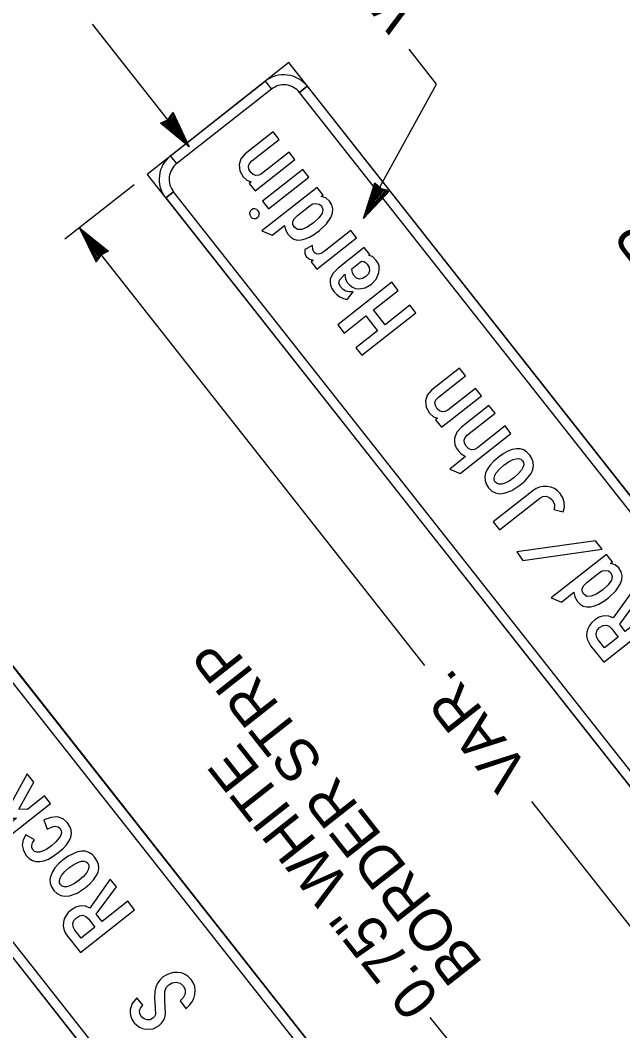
# Model space of a CAD drawing. Extents: x 671946 to 673995, y 1673066 to 1674936.
# Drawn here: x 672488.3 to 672548.4, y 1673831.7 to 1673932.5 of the extents above; entities that cross this region are included whole.
import ezdxf

# ---------------------------------------------------------------- set-up
doc = ezdxf.new("R2010")
doc.units = 0
doc.layers.add('C-ANNO-SYMB', color=7, linetype='Continuous')
doc.layers.add('Level 1', color=7, linetype='Continuous')

msp = doc.modelspace()

# ---------------------------------------------------------------- linework, layer by layer
at = {"layer": 'C-ANNO-SYMB'}
for p, q in [((672515.08, 1673928.32), (672500.95, 1673917.17)), ((672593.09, 1673829.37), (672515.08, 1673928.32)), ((672503.3, 1673919.03), (672512.73, 1673926.46)), ((672512.73, 1673926.46), (672513.35, 1673925.68)), ((672512.73, 1673926.46), (672513.35, 1673925.68)), ((672513.35, 1673925.68), (672503.92, 1673918.25)), ((672513.35, 1673925.68), (672513.35, 1673925.68)), ((672513.35, 1673925.68), (672513.35, 1673925.68)), ((672516.16, 1673925.34), (672516.94, 1673925.96)), ((672516.94, 1673925.96), (672516.16, 1673925.34)), ((672516.94, 1673925.96), (672591.23, 1673831.72)), ((672590.45, 1673831.11), (672516.16, 1673925.34)), ((672503.92, 1673918.25), (672503.3, 1673919.03)), ((672503.92, 1673918.25), (672503.3, 1673919.03)), ((672503.92, 1673918.25), (672503.3, 1673919.03)), ((672500.95, 1673917.17), (672578.96, 1673818.23)), ((672502.81, 1673914.82), (672503.59, 1673915.44)), ((672503.59, 1673915.44), (672502.81, 1673914.82)), ((672503.59, 1673915.44), (672503.59, 1673915.44)), ((672503.59, 1673915.44), (672503.59, 1673915.44)), ((672577.88, 1673821.2), (672503.59, 1673915.44)), ((672502.81, 1673914.82), (672577.1, 1673820.58)), ((672546.83, 1673792.9), (672468.82, 1673891.85)), ((672470.68, 1673889.49), (672544.97, 1673795.25)), ((672544.19, 1673794.63), (672469.89, 1673888.87)), ((672454.69, 1673880.7), (672532.69, 1673781.75)), ((672456.54, 1673878.35), (672530.83, 1673784.11)), ((672531.62, 1673784.73), (672457.33, 1673878.97))]:
    msp.add_line(p, q, dxfattribs=at)
for points in [[(672515.71, 1673918.65), (672515.13, 1673919.39), (672512.38, 1673917.23), (672512.11, 1673917.08), (672511.82, 1673917.05), (672511.54, 1673917.15), (672511.3, 1673917.36), (672511.12, 1673917.68), (672511.07, 1673917.98), (672511.18, 1673918.26), (672511.42, 1673918.52), (672514.13, 1673920.66), (672513.52, 1673921.42), (672510.73, 1673919.22), (672510.31, 1673918.73), (672510.14, 1673918.14), (672510.22, 1673917.52), (672510.55, 1673916.93), (672510.92, 1673916.58), (672511.33, 1673916.41), (672511.15, 1673916.27), (672511.74, 1673915.52)], [(672517.1, 1673916.89), (672516.5, 1673917.65), (672512.48, 1673914.49), (672513.08, 1673913.72)], [(672511.98, 1673912.86), (672512.1, 1673912.99), (672512.15, 1673913.17), (672512.13, 1673913.36), (672512.04, 1673913.53), (672511.89, 1673913.66), (672511.71, 1673913.73), (672511.53, 1673913.72), (672511.37, 1673913.63), (672511.24, 1673913.49), (672511.18, 1673913.31), (672511.2, 1673913.12), (672511.3, 1673912.94), (672511.44, 1673912.81), (672511.63, 1673912.76), (672511.81, 1673912.77)], [(672521.86, 1673910.84), (672521.28, 1673911.58), (672518.63, 1673909.48), (672518.32, 1673909.28), (672518.05, 1673909.2), (672517.82, 1673909.24), (672517.62, 1673909.39), (672517.49, 1673909.69), (672517.46, 1673910.08), (672516.69, 1673909.67), (672516.7, 1673909.26), (672516.84, 1673908.96), (672517.15, 1673908.7), (672517.51, 1673908.61), (672517.31, 1673908.45), (672517.9, 1673907.71)], [(672527.76, 1673903.37), (672527.18, 1673904.11), (672524.7, 1673902.16), (672523.53, 1673903.64), (672526.01, 1673905.59), (672525.36, 1673906.41), (672519.97, 1673902.16), (672520.62, 1673901.34), (672522.78, 1673903.04), (672523.95, 1673901.56), (672521.78, 1673899.86), (672522.37, 1673899.12)], [(672534.3, 1673895.07), (672533.72, 1673895.81), (672530.97, 1673893.64), (672530.7, 1673893.5), (672530.41, 1673893.47), (672530.13, 1673893.57), (672529.9, 1673893.78), (672529.71, 1673894.1), (672529.67, 1673894.4), (672529.77, 1673894.68), (672530.01, 1673894.94), (672532.72, 1673897.08), (672532.12, 1673897.84), (672529.32, 1673895.64), (672528.9, 1673895.15), (672528.73, 1673894.56), (672528.81, 1673893.94), (672529.14, 1673893.35), (672529.51, 1673892.99), (672529.92, 1673892.83), (672529.74, 1673892.69), (672530.33, 1673891.94)], [(672532.32, 1673891.94), (672531.86, 1673891.44), (672531.63, 1673890.85), (672531.61, 1673890.52), (672531.66, 1673890.21), (672531.78, 1673889.9), (672531.97, 1673889.61), (672532.29, 1673889.3), (672532.72, 1673889.01), (672531.14, 1673887.77), (672532.17, 1673887.32), (672537.25, 1673891.33), (672536.67, 1673892.07), (672533.92, 1673889.9), (672533.62, 1673889.73), (672533.33, 1673889.69), (672533.06, 1673889.79), (672532.8, 1673890.04), (672532.62, 1673890.35), (672532.58, 1673890.64), (672532.68, 1673890.92), (672532.92, 1673891.17), (672535.67, 1673893.34), (672535.06, 1673894.1)], [(672542.45, 1673883.49), (672542.58, 1673883.95), (672542.55, 1673884.45), (672542.41, 1673884.91), (672542.15, 1673885.33), (672541.88, 1673885.61), (672541.58, 1673885.83), (672541.24, 1673885.97), (672540.86, 1673886.04), (672540.47, 1673886.04), (672540.11, 1673885.96), (672539.76, 1673885.82), (672539.43, 1673885.6), (672535.48, 1673882.49), (672536.1, 1673881.7), (672540.12, 1673884.88), (672540.43, 1673885.04), (672540.78, 1673885.05), (672541.11, 1673884.94), (672541.37, 1673884.71), (672541.51, 1673884.48), (672541.58, 1673884.24), (672541.59, 1673883.98), (672541.52, 1673883.72)], [(672546.35, 1673879.79), (672545.69, 1673880.62), (672537.83, 1673879.5), (672538.45, 1673878.63)], [(672491.33, 1673854.41), (672490.74, 1673855.15), (672489.03, 1673853.8), (672488.17, 1673853.83), (672489.66, 1673856.53), (672489.01, 1673857.35), (672487.06, 1673853.82), (672485.28, 1673853.82), (672486.04, 1673852.95), (672487.92, 1673852.93), (672485.25, 1673850.82), (672486.25, 1673850.41)], [(672490.99, 1673851.84), (672491.42, 1673852.05), (672491.78, 1673852.13), (672492.08, 1673852.07), (672492.3, 1673851.89), (672492.4, 1673851.7), (672492.42, 1673851.48), (672492.35, 1673851.23), (672492.18, 1673850.96), (672491.87, 1673850.57), (672491.43, 1673850.19), (672490.96, 1673849.86), (672490.51, 1673849.64), (672490.21, 1673849.55), (672489.95, 1673849.54), (672489.74, 1673849.6), (672489.58, 1673849.74), (672489.46, 1673849.97), (672489.45, 1673850.21), (672489.54, 1673850.48), (672489.74, 1673850.76), (672488.86, 1673851.26), (672488.59, 1673850.77), (672488.51, 1673850.25), (672488.62, 1673849.72), (672488.91, 1673849.22), (672489.2, 1673848.92), (672489.52, 1673848.72), (672489.87, 1673848.61), (672490.25, 1673848.6), (672490.67, 1673848.68), (672491.11, 1673848.86), (672491.59, 1673849.13), (672492.1, 1673849.5), (672492.56, 1673849.89), (672492.92, 1673850.28), (672493.18, 1673850.66), (672493.34, 1673851.04), (672493.41, 1673851.4), (672493.38, 1673851.77), (672493.26, 1673852.12), (672493.03, 1673852.47), (672492.57, 1673852.88), (672492.02, 1673853.07), (672491.38, 1673853.02), (672490.65, 1673852.76)], [(672504.83, 1673833.95), (672504.88, 1673833.99), (672505.19, 1673834.27), (672505.43, 1673834.59), (672505.61, 1673834.94), (672505.72, 1673835.33), (672505.76, 1673835.74), (672505.71, 1673836.13), (672505.58, 1673836.49), (672505.35, 1673836.84), (672505.07, 1673837.14), (672504.75, 1673837.35), (672504.39, 1673837.49), (672503.99, 1673837.55), (672503.6, 1673837.54), (672503.22, 1673837.45), (672502.86, 1673837.29), (672502.51, 1673837.06), (672502.22, 1673836.78), (672502, 1673836.46), (672501.84, 1673836.08), (672501.74, 1673835.66), (672501.71, 1673834.98), (672501.77, 1673834.01), (672501.79, 1673833.36), (672501.7, 1673833.14), (672501.54, 1673832.97), (672501.27, 1673832.83), (672500.95, 1673832.81), (672500.65, 1673832.92), (672500.4, 1673833.13), (672500.24, 1673833.43), (672500.21, 1673833.73), (672500.31, 1673833.98), (672500.52, 1673834.27), (672499.93, 1673835.02), (672499.47, 1673834.46), (672499.27, 1673833.84), (672499.26, 1673833.49), (672499.33, 1673833.16), (672499.47, 1673832.83), (672499.67, 1673832.52), (672499.92, 1673832.27), (672500.19, 1673832.08), (672500.51, 1673831.94), (672500.86, 1673831.88), (672501.55, 1673831.92), (672502.16, 1673832.24), (672502.41, 1673832.48), (672502.6, 1673832.75), (672502.72, 1673833.06), (672502.79, 1673833.4), (672502.72, 1673834.77), (672502.71, 1673835.29), (672502.74, 1673835.64), (672502.87, 1673836.03), (672503.11, 1673836.32), (672503.47, 1673836.52), (672503.86, 1673836.58), (672504.26, 1673836.48), (672504.57, 1673836.22), (672504.76, 1673835.83), (672504.74, 1673835.4), (672504.56, 1673835.02), (672504.24, 1673834.7)]]:
    msp.add_lwpolyline(points, close=True, dxfattribs=at)
for points in [[(672518.51, 1673915.11), (672517.91, 1673915.87), (672512.4, 1673911.54), (672513.43, 1673911.1), (672514.67, 1673912.08), (672514.76, 1673911.63), (672515.04, 1673911.16), (672515.31, 1673910.89), (672515.61, 1673910.71), (672515.94, 1673910.62), (672516.31, 1673910.63), (672516.72, 1673910.73), (672517.16, 1673910.92), (672517.64, 1673911.2), (672518.14, 1673911.57), (672518.85, 1673912.22), (672519.3, 1673912.88), (672519.45, 1673913.31), (672519.48, 1673913.73), (672519.38, 1673914.13), (672519.15, 1673914.51), (672518.78, 1673914.82), (672518.32, 1673914.96), (672518.51, 1673915.11)], [(672517.21, 1673914.06), (672517.49, 1673914.22), (672517.8, 1673914.27), (672518.12, 1673914.21), (672518.36, 1673914.02), (672518.5, 1673913.67), (672518.41, 1673913.28), (672518.09, 1673912.83), (672517.55, 1673912.34), (672516.91, 1673911.9), (672516.38, 1673911.68), (672515.97, 1673911.67), (672515.66, 1673911.89), (672515.51, 1673912.18), (672515.51, 1673912.47), (672515.66, 1673912.77), (672515.96, 1673913.07), (672517.21, 1673914.06)], [(672523.18, 1673909.17), (672522.62, 1673909.88), (672520, 1673907.81), (672519.49, 1673907.29), (672519.23, 1673906.73), (672519.21, 1673906.41), (672519.25, 1673906.1), (672519.38, 1673905.78), (672519.59, 1673905.47), (672519.87, 1673905.17), (672520.19, 1673904.94), (672520.54, 1673904.78), (672520.93, 1673904.68), (672521.5, 1673905.45), (672521.12, 1673905.45), (672520.79, 1673905.53), (672520.51, 1673905.68), (672520.27, 1673905.91), (672520.08, 1673906.29), (672520.14, 1673906.63), (672520.68, 1673907.2), (672520.76, 1673906.72), (672520.95, 1673906.36), (672521.19, 1673906.1), (672521.46, 1673905.91), (672521.76, 1673905.79), (672522.08, 1673905.75), (672522.72, 1673905.85), (672523.34, 1673906.21), (672523.81, 1673906.72), (672524.08, 1673907.34), (672524.12, 1673907.68), (672524.1, 1673908), (672523.99, 1673908.31), (672523.81, 1673908.59), (672523.44, 1673908.96), (672523.07, 1673909.09), (672523.18, 1673909.17)], [(672521.38, 1673907.76), (672522.21, 1673908.41), (672522.38, 1673908.5), (672522.56, 1673908.49), (672522.74, 1673908.39), (672522.92, 1673908.2), (672523.1, 1673907.88), (672523.14, 1673907.55), (672523.03, 1673907.24), (672522.78, 1673906.97), (672522.45, 1673906.77), (672522.14, 1673906.72), (672521.86, 1673906.81), (672521.61, 1673907.04), (672521.44, 1673907.36), (672521.38, 1673907.76)], [(672535.96, 1673888.93), (672535.5, 1673888.53), (672535.13, 1673888.13), (672534.87, 1673887.74), (672534.7, 1673887.36), (672534.64, 1673886.98), (672534.67, 1673886.61), (672534.8, 1673886.24), (672535.02, 1673885.89), (672535.35, 1673885.57), (672535.71, 1673885.38), (672536.13, 1673885.3), (672536.59, 1673885.35), (672537.34, 1673885.63), (672538.15, 1673886.15), (672538.62, 1673886.56), (672538.98, 1673886.95), (672539.26, 1673887.34), (672539.43, 1673887.72), (672539.5, 1673888.1), (672539.47, 1673888.46), (672539.35, 1673888.82), (672539.12, 1673889.17), (672538.84, 1673889.47), (672538.52, 1673889.67), (672538.17, 1673889.79), (672537.79, 1673889.8), (672537.38, 1673889.73), (672536.94, 1673889.55), (672536.46, 1673889.29), (672535.96, 1673888.93)], [(672536.53, 1673888.15), (672537.01, 1673888.48), (672537.46, 1673888.71), (672537.77, 1673888.8), (672538.02, 1673888.81), (672538.24, 1673888.75), (672538.4, 1673888.6), (672538.51, 1673888.41), (672538.52, 1673888.19), (672538.45, 1673887.94), (672538.3, 1673887.66), (672537.98, 1673887.28), (672537.54, 1673886.89), (672537.07, 1673886.57), (672536.63, 1673886.35), (672536.33, 1673886.26), (672536.07, 1673886.25), (672535.86, 1673886.32), (672535.69, 1673886.46), (672535.59, 1673886.66), (672535.58, 1673886.87), (672535.64, 1673887.12), (672535.79, 1673887.39), (672536.11, 1673887.77), (672536.53, 1673888.15)], [(672547.37, 1673878.5), (672546.77, 1673879.26), (672541.27, 1673874.93), (672542.29, 1673874.49), (672543.54, 1673875.47), (672543.62, 1673875.02), (672543.9, 1673874.55), (672544.17, 1673874.28), (672544.47, 1673874.1), (672544.81, 1673874.01), (672545.18, 1673874.02), (672545.58, 1673874.12), (672546.02, 1673874.3), (672546.5, 1673874.58), (672547.01, 1673874.95), (672547.71, 1673875.61), (672548.16, 1673876.27), (672548.31, 1673876.7), (672548.34, 1673877.12), (672548.24, 1673877.52), (672548.01, 1673877.9), (672547.64, 1673878.2), (672547.18, 1673878.35), (672547.37, 1673878.5)], [(672546.07, 1673877.44), (672546.35, 1673877.6), (672546.66, 1673877.66), (672546.98, 1673877.6), (672547.22, 1673877.41), (672547.36, 1673877.06), (672547.27, 1673876.67), (672546.96, 1673876.22), (672546.41, 1673875.73), (672545.77, 1673875.29), (672545.25, 1673875.07), (672544.83, 1673875.06), (672544.52, 1673875.28), (672544.37, 1673875.57), (672544.37, 1673875.86), (672544.52, 1673876.16), (672544.82, 1673876.46), (672546.07, 1673877.44)], [(672551.9, 1673872.75), (672551.23, 1673873.59), (672548.66, 1673871.57), (672548.1, 1673872.29), (672550.11, 1673875.02), (672549.5, 1673875.79), (672547.46, 1673872.91), (672547.01, 1673873.1), (672546.51, 1673873.12), (672546.05, 1673872.99), (672545.62, 1673872.73), (672545.31, 1673872.45), (672545.07, 1673872.16), (672544.91, 1673871.84), (672544.82, 1673871.51), (672544.8, 1673871.16), (672544.86, 1673870.8), (672545.01, 1673870.45), (672545.23, 1673870.11), (672546.51, 1673868.5), (672551.9, 1673872.75)], [(672547.95, 1673871.01), (672546.58, 1673869.93), (672545.96, 1673870.72), (672545.78, 1673871.03), (672545.75, 1673871.36), (672545.86, 1673871.68), (672546.1, 1673871.95), (672546.44, 1673872.15), (672546.75, 1673872.19), (672547.04, 1673872.08), (672547.31, 1673871.83), (672547.95, 1673871.01)], [(672492.6, 1673848.77), (672492.13, 1673848.37), (672491.77, 1673847.97), (672491.51, 1673847.58), (672491.34, 1673847.2), (672491.27, 1673846.82), (672491.3, 1673846.45), (672491.43, 1673846.09), (672491.66, 1673845.73), (672491.98, 1673845.41), (672492.35, 1673845.22), (672492.76, 1673845.14), (672493.22, 1673845.19), (672493.98, 1673845.47), (672494.78, 1673845.99), (672495.25, 1673846.4), (672495.62, 1673846.79), (672495.89, 1673847.18), (672496.06, 1673847.56), (672496.14, 1673847.94), (672496.11, 1673848.3), (672495.98, 1673848.66), (672495.76, 1673849.01), (672495.47, 1673849.31), (672495.15, 1673849.52), (672494.8, 1673849.63), (672494.42, 1673849.64), (672494.01, 1673849.57), (672493.57, 1673849.39), (672493.1, 1673849.13), (672492.6, 1673848.77)], [(672493.16, 1673847.99), (672493.64, 1673848.33), (672494.1, 1673848.56), (672494.4, 1673848.64), (672494.66, 1673848.65), (672494.87, 1673848.59), (672495.04, 1673848.44), (672495.14, 1673848.25), (672495.15, 1673848.03), (672495.09, 1673847.78), (672494.93, 1673847.51), (672494.62, 1673847.12), (672494.18, 1673846.74), (672493.71, 1673846.41), (672493.26, 1673846.19), (672492.96, 1673846.1), (672492.7, 1673846.09), (672492.49, 1673846.16), (672492.33, 1673846.31), (672492.23, 1673846.5), (672492.21, 1673846.72), (672492.28, 1673846.96), (672492.42, 1673847.23), (672492.74, 1673847.61), (672493.16, 1673847.99)], [(672499.69, 1673843.8), (672499.02, 1673844.65), (672496.46, 1673842.63), (672495.89, 1673843.35), (672497.9, 1673846.07), (672497.29, 1673846.85), (672495.25, 1673843.97), (672494.8, 1673844.16), (672494.3, 1673844.18), (672493.84, 1673844.05), (672493.41, 1673843.79), (672493.1, 1673843.51), (672492.87, 1673843.21), (672492.7, 1673842.9), (672492.61, 1673842.57), (672492.59, 1673842.21), (672492.66, 1673841.86), (672492.8, 1673841.51), (672493.03, 1673841.17), (672494.3, 1673839.55), (672499.69, 1673843.8)], [(672495.75, 1673842.07), (672494.37, 1673840.98), (672493.75, 1673841.77), (672493.58, 1673842.09), (672493.54, 1673842.42), (672493.65, 1673842.74), (672493.9, 1673843.01), (672494.23, 1673843.2), (672494.54, 1673843.25), (672494.83, 1673843.14), (672495.1, 1673842.88), (672495.75, 1673842.07)]]:
    msp.add_lwpolyline(points, dxfattribs=at)
for centre, radius, start, end in [((672514.59, 1673924.1), 3, 38.2506, 128.2508), ((672514.59, 1673924.1), 2, 38.2506, 128.2508), ((672505.16, 1673916.68), 3, 128.2505, 218.2508), ((672505.16, 1673916.68), 2, 128.2505, 218.2508)]:
    msp.add_arc(centre, radius, start, end, dxfattribs=at)
at = {"layer": 'Level 1'}
for p, q in [((672505.16, 1673919.91), (672495.5, 1673932.16)), ((672503.52, 1673923.4), (672505.16, 1673919.91)), ((672502.3, 1673922.29), (672503.06, 1673922.66)), ((672502.44, 1673922.27), (672503.02, 1673922.6)), ((672502.61, 1673922.26), (672502.87, 1673922.39)), ((672502.74, 1673922.26), (672503.46, 1673922.92)), ((672502.87, 1673922.39), (672503.46, 1673922.92)), ((672502.88, 1673922.3), (672503.39, 1673922.75)), ((672503.29, 1673922.67), (672503.01, 1673922.3)), ((672503.02, 1673922.6), (672503.5, 1673923.26)), ((672503.02, 1673922.24), (672503.35, 1673922.59)), ((672503.06, 1673922.66), (672503.38, 1673922.9)), ((672503.15, 1673922.2), (672503.3, 1673922.48)), ((672503.29, 1673922.31), (672503.29, 1673922.67)), ((672503.3, 1673922.48), (672503.56, 1673921.96)), ((672503.35, 1673922.59), (672503.85, 1673921.61)), ((672503.38, 1673922.9), (672503.57, 1673923.21)), ((672503.39, 1673922.75), (672504.11, 1673921.22)), ((672503.5, 1673923.26), (672503.43, 1673923.04)), ((672503.43, 1673923.04), (672503.53, 1673923.04)), ((672503.46, 1673922.92), (672504.44, 1673920.78)), ((672503.46, 1673922.92), (672504.56, 1673920.71)), ((672503.53, 1673923.04), (672504.89, 1673920.17)), ((672503.57, 1673923.21), (672504.8, 1673920.33)), ((672505.16, 1673919.91), (672502.3, 1673922.29)), ((672504.92, 1673920.13), (672502.44, 1673922.27)), ((672504.66, 1673920.49), (672502.61, 1673922.26)), ((672504.44, 1673920.78), (672502.74, 1673922.26)), ((672504.56, 1673920.71), (672502.88, 1673922.3)), ((672503.01, 1673922.3), (672503.76, 1673921.78)), ((672504.11, 1673921.22), (672503.02, 1673922.24)), ((672503.85, 1673921.61), (672503.15, 1673922.2)), ((672503.22, 1673922.23), (672503.29, 1673922.31)), ((672503.56, 1673921.96), (672503.22, 1673922.23)), ((672503.76, 1673921.78), (672503.85, 1673921.52)), ((672522.54, 1673912.78), (672523.66, 1673916.33)), ((672523.66, 1673916.33), (672524.3, 1673915.76)), ((672499.66, 1673916.14), (672492.76, 1673910.7)), ((672525.2, 1673915.58), (672522.54, 1673912.78)), ((672522.66, 1673913.08), (672523.7, 1673916.18)), ((672524.83, 1673915.47), (672522.69, 1673913.12)), ((672525, 1673915.5), (672522.81, 1673913.27)), ((672522.89, 1673913.46), (672523.75, 1673916.03)), ((672523.06, 1673913.63), (672523.89, 1673915.79)), ((672524.69, 1673915.5), (672523.06, 1673913.63)), ((672523.08, 1673913.78), (672523.8, 1673915.9)), ((672524.69, 1673915.5), (672523.08, 1673913.78)), ((672523.36, 1673914.25), (672523.89, 1673915.64)), ((672524.5, 1673915.49), (672523.36, 1673914.25)), ((672523.63, 1673914.64), (672523.9, 1673915.51)), ((672524.34, 1673915.47), (672523.63, 1673914.64)), ((672523.7, 1673916.18), (672524.22, 1673915.78)), ((672523.94, 1673915.67), (672523.74, 1673914.78)), ((672523.75, 1673916.03), (672523.98, 1673915.83)), ((672523.8, 1673915.9), (672524.69, 1673915.5)), ((672524.22, 1673915.47), (672523.83, 1673915.04)), ((672523.83, 1673915.04), (672523.96, 1673915.45)), ((672523.89, 1673915.79), (672524.5, 1673915.49)), ((672523.89, 1673915.64), (672524.34, 1673915.47)), ((672523.9, 1673915.51), (672524.22, 1673915.47)), ((672524.39, 1673915.56), (672523.94, 1673915.67)), ((672523.96, 1673915.45), (672524.06, 1673915.42)), ((672523.98, 1673915.83), (672524.69, 1673915.5)), ((672524.06, 1673915.42), (672524.39, 1673915.56)), ((672524.22, 1673915.78), (672525.01, 1673915.58)), ((672524.3, 1673915.76), (672524.64, 1673915.56)), ((672524.64, 1673915.56), (672525, 1673915.5)), ((672524.79, 1673915.56), (672524.83, 1673915.47)), ((672523.54, 1673914.6), (672523.33, 1673914.14)), ((672523.33, 1673914.14), (672523.66, 1673914.49)), ((672523.74, 1673914.78), (672523.54, 1673914.6)), ((672522.87, 1673913.23), (672523.46, 1673913.91)), ((672523.46, 1673913.91), (672522.89, 1673913.46)), ((672495.91, 1673908.37), (672494.2, 1673911.84)), ((672494.2, 1673911.84), (672497.11, 1673909.51)), ((672528.67, 1673868.18), (672494.24, 1673911.86)), ((672494.56, 1673911.41), (672494.44, 1673911.62)), ((672494.44, 1673911.62), (672496.96, 1673909.53)), ((672495.89, 1673908.73), (672494.47, 1673911.58)), ((672494.47, 1673911.58), (672494.5, 1673911.37)), ((672494.5, 1673911.37), (672494.92, 1673910.57)), ((672495.85, 1673908.57), (672494.56, 1673911.41)), ((672494.92, 1673910.57), (672494.71, 1673911.27)), ((672494.71, 1673911.27), (672496.79, 1673909.53)), ((672495.96, 1673908.85), (672494.81, 1673911.05)), ((672494.81, 1673911.05), (672496.53, 1673909.49)), ((672495.96, 1673908.85), (672494.94, 1673910.98)), ((672494.94, 1673910.98), (672496.66, 1673909.53)), ((672495.54, 1673910.25), (672495.19, 1673910.61)), ((672495.19, 1673910.61), (672495.4, 1673910.17)), ((672496.02, 1673909.03), (672495.28, 1673910.54)), ((672495.28, 1673910.54), (672496.38, 1673909.55)), ((672495.64, 1673909.99), (672495.54, 1673910.25)), ((672496.06, 1673909.19), (672495.55, 1673910.15)), ((672495.55, 1673910.15), (672496.26, 1673909.58)), ((672496.4, 1673909.49), (672495.64, 1673909.99)), ((672496.11, 1673909.3), (672495.84, 1673909.82)), ((672495.84, 1673909.82), (672496.18, 1673909.55)), ((672496.66, 1673909.53), (672495.96, 1673908.85)), ((672496.53, 1673909.4), (672495.96, 1673908.85)), ((672496.53, 1673909.49), (672496.02, 1673909.03)), ((672496.38, 1673909.55), (672496.06, 1673909.19)), ((672496.26, 1673909.58), (672496.11, 1673909.3)), ((672496.18, 1673909.55), (672496.11, 1673909.47)), ((672496.11, 1673909.47), (672496.13, 1673909.11)), ((672496.13, 1673909.11), (672496.4, 1673909.49)), ((672497.11, 1673909.51), (672496.35, 1673909.12)), ((672496.96, 1673909.53), (672496.4, 1673909.19)), ((672496.79, 1673909.53), (672496.53, 1673909.4)), ((672496.04, 1673908.88), (672495.85, 1673908.57)), ((672495.99, 1673908.74), (672495.89, 1673908.73)), ((672496.4, 1673909.19), (672495.92, 1673908.52)), ((672496.35, 1673909.12), (672496.04, 1673908.88)), ((672572.2, 1673812.9), (672539.32, 1673854.61))]:
    msp.add_line(p, q, dxfattribs=at)
for points in [[(672523.68, 1673914.99), (672529.84, 1673926.16), (672527.1, 1673929.65)], [(672523.21, 1673821.92), (672532.33, 1673829.18), (672529.19, 1673833.04)]]:
    msp.add_lwpolyline(points, dxfattribs=at)

# ---------------------------------------------------------------- texts
for s, p in [('WHITE TEXT ON', (672528.38, 1673933.62)), ('BORDER STRIP', (672576.68, 1673880.31)), ('BORDER STRIP', (672534.55, 1673838.44)), ('VAR.', (672539.22, 1673857.77)), ('0.75" WHITE ', (672530.26, 1673835.05))]:
    msp.add_text(s, height=4.2, rotation=128.2505, dxfattribs=at).set_placement(p)

doc.saveas('drawing.dxf')
